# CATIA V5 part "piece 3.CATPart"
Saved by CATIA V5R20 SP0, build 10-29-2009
Part number: piece 3
Bounding box of the stored display mesh (mm): x -30 to 30, y -160 to 19.99, z 0 to 10
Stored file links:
  D:\Dropbox\IAO_2011\MMS_GR1\jdubreuilr\jdubreuilr\jdubreuilr\piece 3.CATPart
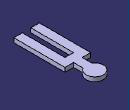
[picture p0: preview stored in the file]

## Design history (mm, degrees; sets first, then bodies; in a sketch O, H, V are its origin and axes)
Set1
  Point1: type OnPlane, Support xy-plane, H 0, V 0, Direction (1, 0, 0)
  Line1: type Normal, RefPoint Point1, RefSkin end face of Pad1, Start 0, End 20
Body1 (main body)
  Sketch1 on xy-plane, origin (0, 0, 0), H (1, 0, 0), V (0, 1, 0)
    line L1 (-10, -17.3205) -> (-10, -40)
    point P1 (-10, -17.3205)
    point P2 (-10, -40)
    line L2 (10, -17.3205) -> (10, -40)
    point P3 (10, -17.3205)
    point P4 (10, -40)
    arc A1 centre (0, 0) radius 20 from (10, -17.3205) to (-10, -17.3205) ccw
    point P5 (-10, -17.3205)
    point P6 (10, -17.3205)
    line L3 (10, -40) -> (30, -40)
    line L4 (-10, -40) -> (-30, -40)
    line L5 (30, -40) -> (30, -160)
    line L6 (30, -160) -> (10, -160)
    line L7 (10, -160) -> (10, -60)
    line L8 (10, -60) -> (-10, -60)
    line L9 (-10, -60) -> (-10, -160)
    point P13 (-10, -160)
    line L10 (-10, -160) -> (-30, -160)
    line L11 (-30, -160) -> (-30, -40)
    radius A1 = 20
    distance V L2 = 10
    distance V L1 = 10
    distance H P4 = 40
    distance P2 H = 40
    distance L8 L3 = 20
    distance L5 L7 = 20
    distance L9 L11 = 20
    distance L7 L9 = 20
    distance H L6 = 160
    vertical: L1 V, L2 V, L5 V, L11 V
    coincidence: P5 L1, P6 L2, P3 P6, P5 P1, P13 L6, L9 L1
    horizontal: L3 H, L4 H, L6 H, L8 H, L10 H
  Pad1: profile Sketch1, direction (0, 0, 1), length 10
